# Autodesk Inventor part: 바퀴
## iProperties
Company: 한국ATC센터
Created: 2015-05
Part Number: 바퀴
Document SubType Name: 모델링
Designer: KYOUNG IL JANG
Vendor: CBT Solutions
Author: KYOUNG IL JANG
Comments: 파생
